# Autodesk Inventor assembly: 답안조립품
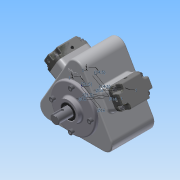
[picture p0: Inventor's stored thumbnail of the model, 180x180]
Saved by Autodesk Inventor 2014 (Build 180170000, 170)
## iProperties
Created: 2015-06
Part Number: 답안조립품
Document SubType Name: Assembly
Designer: Administrator
Mass: 5318.58 g
Surface Area: 2414.93 cm^2
Volume: 1564.62 cm^3
Density: 3.39928 g/cm^3
Author: Administrator
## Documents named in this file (20)
- C:\Users\Administrator\Desktop\350605V1050\답안조립품.iam
- C:\Users\Administrator\Desktop\350605V1050\본체.ipt
- C:\Users\Administrator\Desktop\350605V1050\베어링 NA 4904.ipt
- 베어링 NA 4904.ipt
- C:\Users\Administrator\Desktop\350605V1050\편심축.ipt
- C:\Users\Administrator\Desktop\350605V1050\앞커버.ipt
- C:\Users\Administrator\Desktop\350605V1050\오일실.ipt
- 오일실.ipt
- C:\Users\Administrator\Desktop\350605V1050\M6x0.7x20.ipt
- M6x0.7x20.ipt
- C:\Users\Administrator\Desktop\350605V1050\부시.ipt
- C:\Users\Administrator\Desktop\350605V1050\슬라이드.ipt
- C:\Users\Administrator\Desktop\350605V1050\스프링1.ipt
- C:\Users\Administrator\Desktop\350605V1050\스프링2.ipt
- C:\Users\Administrator\Desktop\350605V1050\스프링3.ipt
- C:\Users\Administrator\Desktop\350605V1050\스프링4.ipt
- C:\Users\Administrator\Desktop\350605V1050\헤더커버.ipt
- 헤더커버.ipt
- C:\Users\Administrator\Desktop\350605V1050\M4x0.5x16.ipt
- M4x0.5x16.ipt
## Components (14 placed, 3 different names)
1. M6x0.7x20:1
2. M6x0.7x20:2
3. M6x0.7x20:3
4. M6x0.7x20:4
5. 헤더커버:1
6. 헤더커버:2
7. M4x0.5x16:1
8. M4x0.5x16:2
9. M4x0.5x16:3
10. M4x0.5x16:4
11. M4x0.5x16:5
12. M4x0.5x16:6
13. M4x0.5x16:7
14. M4x0.5x16:8
